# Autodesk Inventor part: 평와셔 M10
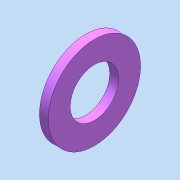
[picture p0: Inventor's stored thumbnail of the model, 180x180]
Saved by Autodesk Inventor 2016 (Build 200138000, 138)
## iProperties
Created: 2024-09
Part Number: 평와셔 M10
Material: 일반
Description: 평면 와셔
Document SubType Name: Modeling
Designer: pc-7
Density: 1 g/cm^3
Appearance: 기본값
Author: jhkim
Sending System: Autodesk Inventor 2025
Preprocessor: ST-DEVELOPER v20
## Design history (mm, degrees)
node "평와셔 M101"
node "솔리드1"
body "Solid1"
